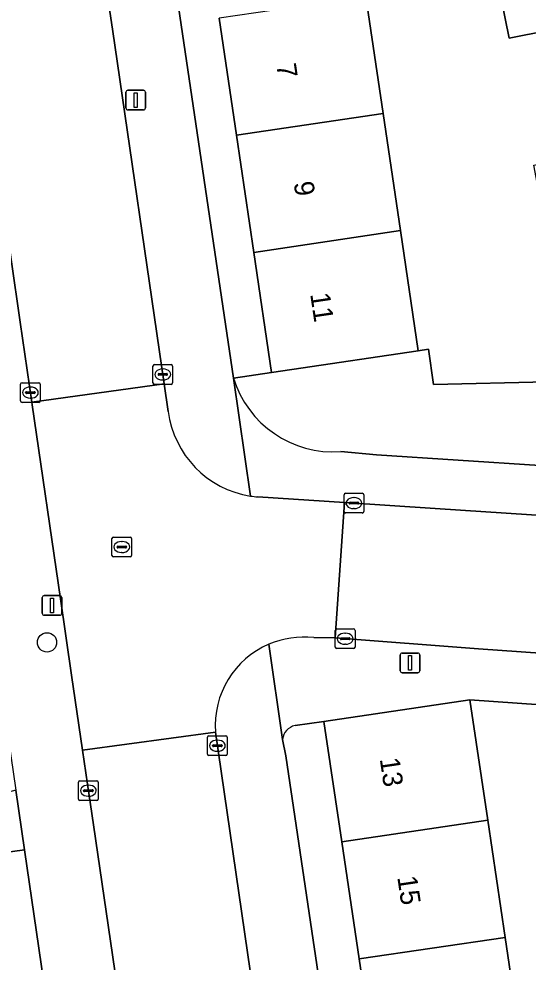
# Model space of a CAD drawing. Extents: x 159053 to 160042, y 380449 to 381423.
# Drawn here: x 159304.08 to 159329.91, y 381110.68 to 381158.52 of the extents above; entities that cross this region are included whole.
import ezdxf

# ---------------------------------------------------------------- set-up
doc = ezdxf.new("R2010")
doc.units = 0
for name, color, linetype in [('IMGEO_Boom', 7, 'Continuous'), ('IMGEO_Erf', 7, 'Continuous'), ('IMGEO_Groenvoorziening', 7, 'Continuous'), ('IMGEO_Kolk', 7, 'Continuous'), ('IMGEO_Lichtmast', 7, 'Continuous'), ('IMGEO_Muur', 7, 'Continuous'), ('IMGEO_Pand', 7, 'Continuous'), ('IMGEO_Pand_nummerreeks', 7, 'Continuous'), ('IMGEO_Parkeervlak_open', 7, 'Continuous'), ('IMGEO_Rijbaan_lokaal_open', 7, 'Continuous'), ('IMGEO_Rioolput', 7, 'Continuous'), ('IMGEO_Voetpad_open', 7, 'Continuous')]:
    doc.layers.add(name, color=color, linetype=linetype)

msp = doc.modelspace()

# ---------------------------------------------------------------- linework, layer by layer
at = {"layer": 'IMGEO_Boom'}
msp.add_circle((159305.508, 381126.893), 0.489, dxfattribs=at)
at = {"layer": 'IMGEO_Erf'}
for points in [[(159308.918, 381181.179), (159314.964, 381140.298), (159316.894, 381140.584), (159315.993, 381146.674), (159315.115, 381152.609), (159314.237, 381158.545)], [(159321.676, 381159.646), (159322.554, 381153.71), (159323.432, 381147.775), (159324.333, 381141.685), (159324.851, 381141.762), (159325.116, 381139.979), (159330.87, 381140.103), (159331.166, 381144.471), (159335.537, 381144.175), (159335.629, 381145.526), (159335.229, 381146.475), (159331.208, 381145.721), (159330.623, 381148.839), (159330.201, 381151.091), (159334.222, 381151.845), (159332.778, 381158.297), (159328.943, 381157.53), (159328.323, 381160.63)], [(159340.611, 381110.412), (159339.666, 381116.792), (159335.611, 381116.19), (159335.2, 381118.957), (159334.796, 381121.68), (159338.851, 381122.282), (159338.721, 381123.156), (159326.952, 381123.978), (159327.858, 381117.868), (159328.738, 381111.933), (159329.618, 381105.998)], [(159317.456, 381121.97), (159317.617, 381121.133), (159322.737, 381086.604), (159324.884, 381086.922), (159323.978, 381093.029), (159323.098, 381098.964), (159322.218, 381104.9), (159321.338, 381110.835), (159320.458, 381116.77), (159319.552, 381122.881), (159318.09, 381122.671)]]:
    msp.add_lwpolyline(points, dxfattribs=at)
msp.add_arc((159318.23, 381121.907), 0.777, 100.3853, 175.3609, dxfattribs=at)
at = {"layer": 'IMGEO_Groenvoorziening'}
for points in [[(159324.851, 381141.762), (159324.333, 381141.685), (159317.925, 381140.737), (159316.894, 381140.584), (159314.964, 381140.298)], [(159320.412, 381136.566), (159322.216, 381136.408), (159330.511, 381135.86), (159330.649, 381137.491), (159330.87, 381140.103), (159325.116, 381139.979), (159324.851, 381141.762)], [(159301.734, 381099.495), (159306.727, 381100.183), (159305.82, 381106.393), (159300.832, 381105.715), (159299.362, 381115.674), (159304.363, 381116.374), (159303.921, 381119.402), (159296.289, 381117.311), (159296.87, 381115.183), (159291.727, 381113.703), (159293.441, 381107.525), (159293.597, 381107.568), (159302.903, 381073.889), (159297.014, 381072.255), (159297.723, 381069.615), (159285.651, 381066.276), (159287.134, 381060.86), (159289.094, 381061.4), (159287.696, 381066.465), (159297.411, 381069.143), (159298.793, 381064.19), (159309.233, 381066.896)]]:
    msp.add_lwpolyline(points, dxfattribs=at)
msp.add_arc((159320.041, 381141.867), 5.314, 197.1744, 274.0016, dxfattribs=at)
at = {"layer": 'IMGEO_Kolk'}
for p, q in [((159310.878, 381140.054), (159310.878, 381140.906)), ((159310.953, 381140.98), (159311.805, 381140.98)), ((159311.366, 381140.76), (159311.391, 381140.76)), ((159311.879, 381140.906), (159311.879, 381140.054)), ((159311.137, 381140.474), (159311.137, 381140.486)), ((159311.575, 381140.437), (159311.177, 381140.437)), ((159311.18, 381140.523), (159311.578, 381140.523)), ((159311.389, 381140.2), (159311.364, 381140.2)), ((159311.621, 381140.486), (159311.621, 381140.474)), ((159304.164, 381139.137), (159304.164, 381139.989)), ((159304.239, 381140.063), (159305.091, 381140.063)), ((159304.652, 381139.843), (159304.677, 381139.843)), ((159305.165, 381139.989), (159305.165, 381139.137)), ((159311.805, 381139.98), (159310.953, 381139.98)), ((159304.423, 381139.557), (159304.423, 381139.569)), ((159304.861, 381139.52), (159304.463, 381139.52)), ((159304.466, 381139.606), (159304.864, 381139.606)), ((159304.675, 381139.283), (159304.65, 381139.283)), ((159304.907, 381139.569), (159304.907, 381139.557)), ((159305.091, 381139.063), (159304.239, 381139.063)), ((159320.648, 381134.455), (159321.5, 381134.455)), ((159320.573, 381133.529), (159320.573, 381134.381)), ((159320.875, 381133.998), (159321.273, 381133.998)), ((159321.061, 381134.235), (159321.086, 381134.235)), ((159321.574, 381134.381), (159321.574, 381133.529)), ((159320.832, 381133.949), (159320.832, 381133.961)), ((159321.27, 381133.912), (159320.872, 381133.912)), ((159321.084, 381133.675), (159321.059, 381133.675)), ((159321.316, 381133.961), (159321.316, 381133.949)), ((159321.5, 381133.455), (159320.648, 381133.455)), ((159320.13, 381126.651), (159320.13, 381127.503)), ((159320.205, 381127.577), (159321.057, 381127.577)), ((159320.618, 381127.357), (159320.643, 381127.357)), ((159321.131, 381127.503), (159321.131, 381126.651)), ((159320.389, 381127.071), (159320.389, 381127.083)), ((159320.827, 381127.034), (159320.429, 381127.034)), ((159320.432, 381127.12), (159320.83, 381127.12)), ((159320.641, 381126.797), (159320.616, 381126.797)), ((159320.873, 381127.083), (159320.873, 381127.071)), ((159321.057, 381126.577), (159320.205, 381126.577)), ((159313.648, 381121.226), (159313.648, 381122.078)), ((159313.723, 381122.152), (159314.575, 381122.152)), ((159314.649, 381122.078), (159314.649, 381121.226)), ((159313.907, 381121.646), (159313.907, 381121.658)), ((159314.345, 381121.609), (159313.947, 381121.609)), ((159313.95, 381121.695), (159314.348, 381121.695)), ((159314.136, 381121.932), (159314.161, 381121.932)), ((159314.391, 381121.658), (159314.391, 381121.646)), ((159314.575, 381121.152), (159313.723, 381121.152)), ((159314.159, 381121.372), (159314.134, 381121.372)), ((159307.103, 381118.946), (159307.103, 381119.798)), ((159307.178, 381119.872), (159308.03, 381119.872)), ((159307.591, 381119.652), (159307.616, 381119.652)), ((159308.104, 381119.798), (159308.104, 381118.946)), ((159307.362, 381119.366), (159307.362, 381119.378)), ((159307.8, 381119.329), (159307.402, 381119.329)), ((159307.405, 381119.415), (159307.803, 381119.415)), ((159307.846, 381119.378), (159307.846, 381119.366)), ((159308.03, 381118.872), (159307.178, 381118.872)), ((159307.614, 381119.092), (159307.589, 381119.092))]:
    msp.add_line(p, q, dxfattribs=at)
for points in [[(159310.878, 381140.054), (159310.878, 381140.906)], [(159310.953, 381140.98), (159311.805, 381140.98)], [(159311.879, 381140.906), (159311.879, 381140.054)], [(159304.164, 381139.137), (159304.164, 381139.989)], [(159304.239, 381140.063), (159305.091, 381140.063)], [(159305.165, 381139.989), (159305.165, 381139.137)], [(159311.805, 381139.98), (159310.953, 381139.98)], [(159305.091, 381139.063), (159304.239, 381139.063)], [(159320.648, 381134.455), (159321.5, 381134.455)], [(159320.573, 381133.529), (159320.573, 381134.381)], [(159321.574, 381134.381), (159321.574, 381133.529)], [(159321.5, 381133.455), (159320.648, 381133.455)], [(159320.13, 381126.651), (159320.13, 381127.503)], [(159320.205, 381127.577), (159321.057, 381127.577)], [(159321.131, 381127.503), (159321.131, 381126.651)], [(159321.057, 381126.577), (159320.205, 381126.577)], [(159313.648, 381121.226), (159313.648, 381122.078)], [(159313.723, 381122.152), (159314.575, 381122.152)], [(159314.649, 381122.078), (159314.649, 381121.226)], [(159314.575, 381121.152), (159313.723, 381121.152)], [(159307.103, 381118.946), (159307.103, 381119.798)], [(159307.178, 381119.872), (159308.03, 381119.872)], [(159308.104, 381119.798), (159308.104, 381118.946)], [(159308.03, 381118.872), (159307.178, 381118.872)]]:
    msp.add_lwpolyline(points, dxfattribs=at)
for centre, radius, start, end in [((159310.955, 381140.904), 0.0765, 91.552, 178.448), ((159310.955, 381140.904), 0.0765, 91.552, 178.448), ((159311.803, 381140.904), 0.0765, 1.552, 88.448), ((159311.803, 381140.904), 0.0765, 1.552, 88.448), ((159311.177, 381140.483), 0.0403, 85.8775, 175.7526), ((159311.174, 381140.473), 0.0366, 178.938, 274.7102), ((159311.578, 381140.48), 0.043, 264.8664, 352.4533), ((159311.582, 381140.485), 0.0386, 1.7309, 96.639), ((159304.241, 381139.987), 0.0765, 91.552, 178.448), ((159304.241, 381139.987), 0.0765, 91.552, 178.448), ((159305.089, 381139.987), 0.0765, 1.552, 88.448), ((159305.089, 381139.987), 0.0765, 1.552, 88.448), ((159310.955, 381140.056), 0.0765, 181.552, 268.448), ((159310.955, 381140.056), 0.0765, 181.552, 268.448), ((159311.803, 381140.056), 0.0765, 271.552, 358.448), ((159311.803, 381140.056), 0.0765, 271.552, 358.448), ((159304.463, 381139.566), 0.0403, 85.8775, 175.7526), ((159304.46, 381139.556), 0.0366, 178.938, 274.7102), ((159304.864, 381139.563), 0.043, 264.8664, 352.4533), ((159304.868, 381139.568), 0.0386, 1.7309, 96.639), ((159304.241, 381139.139), 0.0765, 181.552, 268.448), ((159304.241, 381139.139), 0.0765, 181.552, 268.448), ((159305.089, 381139.139), 0.0765, 271.552, 358.448), ((159305.089, 381139.139), 0.0765, 271.552, 358.448), ((159320.65, 381134.379), 0.0765, 91.552, 178.448), ((159320.65, 381134.379), 0.0765, 91.552, 178.448), ((159321.498, 381134.379), 0.0765, 1.552, 88.448), ((159321.498, 381134.379), 0.0765, 1.552, 88.448), ((159320.872, 381133.958), 0.0403, 85.8775, 175.7526), ((159321.277, 381133.96), 0.0386, 1.7309, 96.639), ((159320.65, 381133.531), 0.0765, 181.552, 268.448), ((159320.65, 381133.531), 0.0765, 181.552, 268.448), ((159320.869, 381133.948), 0.0366, 178.938, 274.7102), ((159321.273, 381133.955), 0.043, 264.8664, 352.4533), ((159321.498, 381133.531), 0.0765, 271.552, 358.448), ((159321.498, 381133.531), 0.0765, 271.552, 358.448), ((159320.207, 381127.501), 0.0765, 91.552, 178.448), ((159320.207, 381127.501), 0.0765, 91.552, 178.448), ((159321.055, 381127.501), 0.0765, 1.552, 88.448), ((159321.055, 381127.501), 0.0765, 1.552, 88.448), ((159320.429, 381127.08), 0.0403, 85.8775, 175.7526), ((159320.426, 381127.07), 0.0366, 178.938, 274.7102), ((159320.83, 381127.077), 0.043, 264.8664, 352.4533), ((159320.834, 381127.082), 0.0386, 1.7309, 96.639), ((159320.207, 381126.653), 0.0765, 181.552, 268.448), ((159320.207, 381126.653), 0.0765, 181.552, 268.448), ((159321.055, 381126.653), 0.0765, 271.552, 358.448), ((159321.055, 381126.653), 0.0765, 271.552, 358.448), ((159313.725, 381122.076), 0.0765, 91.552, 178.448), ((159313.725, 381122.076), 0.0765, 91.552, 178.448), ((159314.573, 381122.076), 0.0765, 1.552, 88.448), ((159314.573, 381122.076), 0.0765, 1.552, 88.448), ((159313.947, 381121.655), 0.0403, 85.8775, 175.7526), ((159313.944, 381121.645), 0.0366, 178.938, 274.7102), ((159314.348, 381121.652), 0.043, 264.8664, 352.4533), ((159314.352, 381121.657), 0.0386, 1.7309, 96.639), ((159313.725, 381121.228), 0.0765, 181.552, 268.448), ((159313.725, 381121.228), 0.0765, 181.552, 268.448), ((159314.573, 381121.228), 0.0765, 271.552, 358.448), ((159314.573, 381121.228), 0.0765, 271.552, 358.448), ((159307.18, 381119.796), 0.0765, 91.552, 178.448), ((159307.18, 381119.796), 0.0765, 91.552, 178.448), ((159308.028, 381119.796), 0.0765, 1.552, 88.448), ((159308.028, 381119.796), 0.0765, 1.552, 88.448), ((159307.402, 381119.375), 0.0403, 85.8775, 175.7526), ((159307.399, 381119.365), 0.0366, 178.938, 274.7102), ((159307.803, 381119.372), 0.043, 264.8664, 352.4533), ((159307.807, 381119.377), 0.0386, 1.7309, 96.639), ((159307.18, 381118.948), 0.0765, 181.552, 268.448), ((159307.18, 381118.948), 0.0765, 181.552, 268.448), ((159308.028, 381118.948), 0.0765, 271.552, 358.448), ((159308.028, 381118.948), 0.0765, 271.552, 358.448)]:
    msp.add_arc(centre, radius, start, end, dxfattribs=at)
for centre, major_axis, ratio, start_param, end_param in [((159311.365, 381140.48), (-0.387, 0.002), 0.722429, 4.712389, 7.853982), ((159311.39, 381140.48), (-0.39, 0.002), 0.717154, 1.570796, 4.712389), ((159304.651, 381139.563), (-0.387, 0.002), 0.722429, 4.712389, 7.853982), ((159304.676, 381139.563), (-0.39, 0.002), 0.717154, 1.570796, 4.712389), ((159321.06, 381133.955), (-0.387, 0.002), 0.722429, 4.712389, 7.853982), ((159321.085, 381133.955), (-0.39, 0.002), 0.717154, 1.570796, 4.712389), ((159320.617, 381127.077), (-0.387, 0.002), 0.722429, 4.712389, 7.853982), ((159320.642, 381127.077), (-0.39, 0.002), 0.717154, 1.570796, 4.712389), ((159314.135, 381121.652), (-0.387, 0.002), 0.722429, 4.712389, 7.853982), ((159314.16, 381121.652), (-0.39, 0.002), 0.717154, 1.570796, 4.712389), ((159307.59, 381119.372), (-0.387, 0.002), 0.722429, 4.712389, 7.853982), ((159307.615, 381119.372), (-0.39, 0.002), 0.717154, 1.570796, 4.712389)]:
    msp.add_ellipse(centre, major_axis=major_axis, ratio=ratio, start_param=start_param, end_param=end_param, dxfattribs=at)
at = {"layer": 'IMGEO_Lichtmast'}
for p, q in [((159309.508, 381153.997), (159309.508, 381154.797)), ((159309.508, 381154.797), (159309.508, 381153.997)), ((159309.608, 381154.897), (159310.398, 381154.897)), ((159310.398, 381154.897), (159309.608, 381154.897)), ((159310.498, 381154.797), (159310.498, 381153.997)), ((159310.498, 381153.997), (159310.498, 381154.797)), ((159310.398, 381153.897), (159309.608, 381153.897)), ((159309.608, 381153.897), (159310.398, 381153.897)), ((159305.364, 381129.267), (159306.154, 381129.267)), ((159306.154, 381129.267), (159305.364, 381129.267)), ((159305.264, 381128.367), (159305.264, 381129.167)), ((159305.264, 381129.167), (159305.264, 381128.367)), ((159306.254, 381129.167), (159306.254, 381128.367)), ((159306.254, 381128.367), (159306.254, 381129.167)), ((159306.154, 381128.267), (159305.364, 381128.267)), ((159305.364, 381128.267), (159306.154, 381128.267)), ((159323.525, 381126.353), (159324.315, 381126.353)), ((159324.315, 381126.353), (159323.525, 381126.353)), ((159323.425, 381125.453), (159323.425, 381126.253)), ((159323.425, 381126.253), (159323.425, 381125.453)), ((159324.415, 381126.253), (159324.415, 381125.453)), ((159324.415, 381125.453), (159324.415, 381126.253)), ((159324.315, 381125.353), (159323.525, 381125.353)), ((159323.525, 381125.353), (159324.315, 381125.353))]:
    msp.add_line(p, q, dxfattribs=at)
for points in [[(159309.928, 381154.772), (159310.078, 381154.772), (159310.078, 381154.022), (159309.928, 381154.022), (159309.928, 381154.772)], [(159305.684, 381129.142), (159305.834, 381129.142), (159305.834, 381128.392), (159305.684, 381128.392), (159305.684, 381129.142)], [(159323.845, 381126.228), (159323.995, 381126.228), (159323.995, 381125.478), (159323.845, 381125.478), (159323.845, 381126.228)]]:
    msp.add_lwpolyline(points, dxfattribs=at)
for centre, start, end in [((159309.608, 381154.797), 90, 180), ((159309.608, 381154.797), 90, 180), ((159310.398, 381154.797), 0, 90), ((159310.398, 381154.797), 360, 90), ((159309.608, 381153.997), 180, 270), ((159309.608, 381153.997), 180, 270), ((159310.398, 381153.997), 270, 0), ((159310.398, 381153.997), 270, 0), ((159305.364, 381129.167), 90, 180), ((159305.364, 381129.167), 90, 180), ((159306.154, 381129.167), 0, 90), ((159306.154, 381129.167), 360, 90), ((159305.364, 381128.367), 180, 270), ((159305.364, 381128.367), 180, 270), ((159306.154, 381128.367), 270, 0), ((159306.154, 381128.367), 270, 0), ((159323.525, 381126.253), 90, 180), ((159323.525, 381126.253), 90, 180), ((159324.315, 381126.253), 0, 90), ((159324.315, 381126.253), 360, 90), ((159323.525, 381125.453), 180, 270), ((159323.525, 381125.453), 180, 270), ((159324.315, 381125.453), 270, 0), ((159324.315, 381125.453), 270, 0)]:
    msp.add_arc(centre, 0.1, start, end, dxfattribs=at)
at = {"layer": 'IMGEO_Muur'}
msp.add_lwpolyline([(159326.952, 381123.978), (159338.721, 381123.156)], dxfattribs=at)
at = {"layer": 'IMGEO_Pand'}
for points in [[(159332.197, 381161.203), (159328.323, 381160.63), (159328.943, 381157.53), (159332.778, 381158.297)], [(159314.237, 381158.545), (159315.115, 381152.609), (159322.554, 381153.71), (159321.676, 381159.646)], [(159322.554, 381153.71), (159315.115, 381152.609), (159315.993, 381146.674), (159323.432, 381147.775)], [(159315.993, 381146.674), (159316.894, 381140.584), (159317.925, 381140.737), (159324.333, 381141.685), (159323.432, 381147.775)], [(159320.458, 381116.77), (159327.858, 381117.868), (159326.952, 381123.978), (159319.552, 381122.881)], [(159328.738, 381111.933), (159327.858, 381117.868), (159320.458, 381116.77), (159321.338, 381110.835)], [(159328.738, 381111.933), (159321.338, 381110.835), (159322.218, 381104.9), (159329.618, 381105.998)]]:
    msp.add_lwpolyline(points, close=True, dxfattribs=at)
at = {"layer": 'IMGEO_Parkeervlak_open'}
msp.add_lwpolyline([(159299.362, 381115.674), (159300.832, 381105.715), (159305.82, 381106.393), (159304.363, 381116.374)], close=True, dxfattribs=at)
at = {"layer": 'IMGEO_Rijbaan_lokaal_open'}
for points in [[(159298.315, 381182.944), (159298.504, 381181.554), (159299.889, 381172.19), (159300.509, 381167.999), (159301.731, 381159.728), (159302.132, 381157.016), (159302.294, 381155.916), (159302.763, 381152.666), (159304.139, 381143.129), (159304.737, 381139.073), (159311.448, 381140.008), (159308.825, 381157.991), (159308.429, 381160.702), (159305.646, 381179.78)], [(159311.655, 381138.61), (159311.448, 381140.008), (159304.737, 381139.073), (159304.757, 381138.939), (159306.19, 381129.099), (159306.753, 381125.233), (159307.307, 381121.427), (159314.048, 381122.345)], [(159320.6, 381133.986), (159316.193, 381134.269)], [(159319.034, 381127.133), (159320.118, 381127.116), (159320.6, 381133.986)]]:
    msp.add_lwpolyline(points, dxfattribs=at)
for points in [[(159325.192, 381133.689), (159320.6, 381133.986), (159320.118, 381127.116), (159327.397, 381126.568), (159343.979, 381125.396), (159344.386, 381132.385), (159335.084, 381133.041), (159330.073, 381133.355)], [(159307.307, 381121.427), (159307.556, 381119.696), (159307.857, 381117.636), (159309.596, 381105.842), (159310.161, 381102.035), (159310.21, 381101.7), (159310.579, 381099.216), (159311.982, 381089.769), (159312.563, 381085.736), (159313.91, 381076.364), (159314.445, 381072.613), (159321.155, 381073.597), (159317.277, 381100.2), (159316.865, 381103.021), (159314.048, 381122.345)]]:
    msp.add_lwpolyline(points, close=True, dxfattribs=at)
for centre, radius, start, end in [((159316.613, 381139.25), 5, 187.3588, 260.95), ((159316.691, 381139.952), 5.704, 261.2932, 264.9965), ((159318.532, 381122.664), 4.495, 113.1587, 184.0697), ((159318.537, 381122.658), 4.503, 83.657, 113.1823)]:
    msp.add_arc(centre, radius, start, end, dxfattribs=at)
at = {"layer": 'IMGEO_Rioolput'}
for p, q in [((159308.799, 381131.304), (159308.799, 381132.156)), ((159308.874, 381132.23), (159309.726, 381132.23)), ((159309.8, 381132.156), (159309.8, 381131.304)), ((159309.058, 381131.724), (159309.058, 381131.736)), ((159309.496, 381131.687), (159309.098, 381131.687)), ((159309.101, 381131.773), (159309.499, 381131.773)), ((159309.287, 381132.01), (159309.312, 381132.01)), ((159309.542, 381131.736), (159309.542, 381131.724)), ((159309.726, 381131.23), (159308.874, 381131.23)), ((159309.31, 381131.45), (159309.285, 381131.45))]:
    msp.add_line(p, q, dxfattribs=at)
for points in [[(159308.799, 381131.304), (159308.799, 381132.156)], [(159308.874, 381132.23), (159309.726, 381132.23)], [(159309.8, 381132.156), (159309.8, 381131.304)], [(159309.726, 381131.23), (159308.874, 381131.23)]]:
    msp.add_lwpolyline(points, dxfattribs=at)
for centre, radius, start, end in [((159308.876, 381132.154), 0.0765, 91.552, 178.448), ((159308.876, 381132.154), 0.0765, 91.552, 178.448), ((159309.724, 381132.154), 0.0765, 1.552, 88.448), ((159309.724, 381132.154), 0.0765, 1.552, 88.448), ((159309.098, 381131.733), 0.0403, 85.8775, 175.7526), ((159309.095, 381131.723), 0.0366, 178.938, 274.7102), ((159309.499, 381131.73), 0.043, 264.8664, 352.4533), ((159309.503, 381131.735), 0.0386, 1.7309, 96.639), ((159308.876, 381131.306), 0.0765, 181.552, 268.448), ((159308.876, 381131.306), 0.0765, 181.552, 268.448), ((159309.724, 381131.306), 0.0765, 271.552, 358.448), ((159309.724, 381131.306), 0.0765, 271.552, 358.448)]:
    msp.add_arc(centre, radius, start, end, dxfattribs=at)
for centre, major_axis, ratio, start_param, end_param in [((159309.286, 381131.73), (-0.387, 0.002), 0.722429, 4.712389, 7.853982), ((159309.311, 381131.73), (-0.39, 0.002), 0.717154, 1.570796, 4.712389)]:
    msp.add_ellipse(centre, major_axis=major_axis, ratio=ratio, start_param=start_param, end_param=end_param, dxfattribs=at)
at = {"layer": 'IMGEO_Voetpad_open'}
for points in [[(159306.19, 381129.099), (159304.757, 381138.939), (159304.737, 381139.073), (159304.139, 381143.129), (159302.763, 381152.666), (159302.294, 381155.916), (159302.132, 381157.016), (159301.731, 381159.728), (159300.509, 381167.999), (159299.889, 381172.19), (159298.504, 381181.554), (159298.315, 381182.944)], [(159294.912, 381182.231), (159295.246, 381179.972), (159295.395, 381178.961), (159295.968, 381174.666), (159296.278, 381172.341), (159297.057, 381166.506), (159298.503, 381156.571), (159299.3, 381151.1), (159299.795, 381147.696), (159300.386, 381143.634), (159300.637, 381141.908), (159301.249, 381137.708), (159302.473, 381129.318), (159303.192, 381124.392), (159303.921, 381119.402), (159304.363, 381116.374), (159305.82, 381106.393), (159306.727, 381100.183), (159308.151, 381090.241), (159309.044, 381084.316), (159310.329, 381076.855), (159311.284, 381070.128)], [(159315.827, 381134.313), (159314.964, 381140.298), (159308.918, 381181.179)], [(159305.646, 381179.78), (159308.429, 381160.702), (159308.825, 381157.991), (159311.448, 381140.008), (159311.655, 381138.61)], [(159314.964, 381140.298), (159315.827, 381134.313)], [(159363.677, 381133.592), (159360.526, 381133.81), (159336.314, 381135.476), (159334.921, 381135.568), (159330.511, 381135.86), (159322.216, 381136.408), (159320.412, 381136.566)], [(159316.193, 381134.269), (159320.6, 381133.986), (159325.192, 381133.689), (159330.073, 381133.355), (159335.084, 381133.041), (159344.386, 381132.385), (159347.843, 381132.155), (159408.675, 381127.944), (159412.055, 381127.71), (159424.078, 381126.859), (159424.259, 381129.362), (159400.049, 381131.051), (159398.457, 381131.162), (159363.677, 381133.592)], [(159314.75, 381070.473), (159314.445, 381072.613), (159313.91, 381076.364), (159312.563, 381085.736), (159311.982, 381089.769), (159310.579, 381099.216), (159310.21, 381101.7), (159310.161, 381102.035), (159309.596, 381105.842), (159307.857, 381117.636), (159307.556, 381119.696), (159307.307, 381121.427), (159306.753, 381125.233), (159306.19, 381129.099)], [(159316.764, 381126.797), (159317.456, 381121.97)], [(159317.617, 381121.133), (159317.456, 381121.97), (159316.764, 381126.797)], [(159347.425, 381125.142), (159343.979, 381125.396), (159327.397, 381126.568), (159320.118, 381127.116), (159319.034, 381127.133)], [(159318.09, 381122.671), (159319.552, 381122.881), (159326.952, 381123.978), (159338.721, 381123.156), (159340.268, 381123.048), (159352.216, 381122.213), (159352.462, 381120.658), (159359.798, 381121.745), (159368.043, 381121.201), (159371.251, 381120.987)], [(159314.048, 381122.345), (159316.865, 381103.021), (159317.277, 381100.2), (159321.155, 381073.597), (159323.98, 381054.046), (159324.984, 381047.343), (159327.57, 381031.073), (159327.968, 381028.382), (159332.172, 381000), (159334.351, 380985.012), (159334.965, 380980.773), (159335.359, 380978.05), (159335.713, 380975.604), (159337.861, 380961.365), (159337.904, 380961.246), (159343.633, 380962.89)], [(159340.834, 380965.36), (159340.592, 380966.957), (159335.584, 381000), (159323.886, 381079.531), (159323.192, 381083.535), (159322.737, 381086.604), (159317.617, 381121.133)]]:
    msp.add_lwpolyline(points, dxfattribs=at)
for centre, radius, start, end in [((159320.041, 381141.867), 5.314, 197.1744, 274.0016), ((159316.613, 381139.25), 5, 187.3588, 260.95), ((159316.691, 381139.952), 5.704, 261.2932, 264.9965), ((159318.532, 381122.664), 4.495, 113.1587, 184.0697), ((159318.537, 381122.658), 4.503, 83.657, 113.1823), ((159318.23, 381121.907), 0.777, 100.3853, 175.3609)]:
    msp.add_arc(centre, radius, start, end, dxfattribs=at)

# ---------------------------------------------------------------- texts
at = {"layer": 'IMGEO_Pand_nummerreeks'}
for s, rotation, p in [('7', 278.4162, (159317.132, 381156.192)), ('9', 278.4162, (159318.018, 381150.205)), ('11', 278.4162, (159318.853, 381144.561)), ('13', 278.4344, (159322.381, 381120.982)), ('15', 278.4344, (159323.27, 381114.989))]:
    msp.add_text(s, height=1, rotation=rotation, dxfattribs=at).set_placement(p)

doc.saveas('drawing.dxf')
